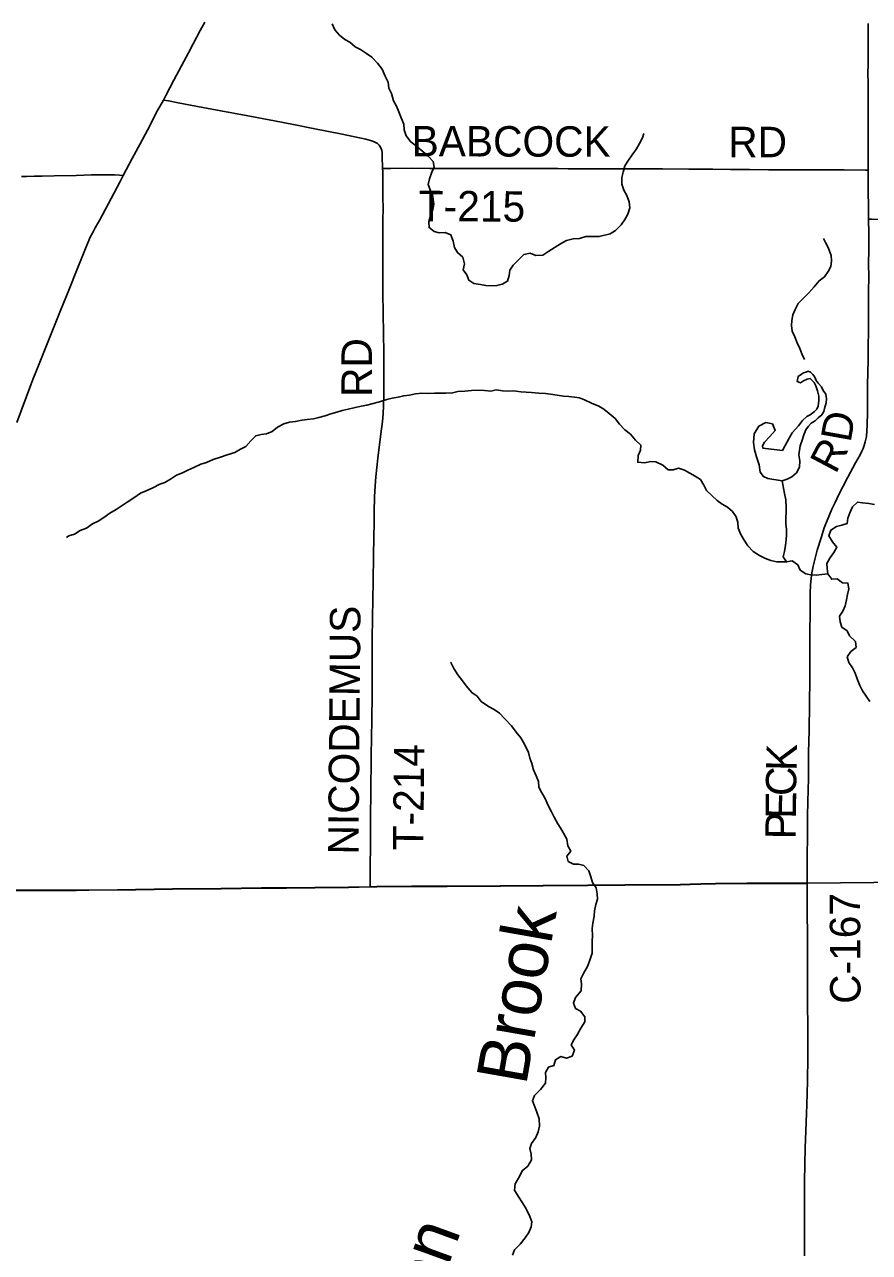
# Model space of a CAD drawing. Extents: x 0 to 34, y 0 to 22.
# Drawn here: x 26.211 to 27.787, y 14.945 to 17.236 of the extents above; entities that cross this region are included whole.
import ezdxf

# ---------------------------------------------------------------- set-up
doc = ezdxf.new("R2010")
doc.units = 0
for name, color, linetype in [('GM_X_Corporation', 7, 'Continuous'), ('GM_X_County_Road', 7, 'Continuous'), ('GM_X_County_Road_Text', 7, 'Continuous'), ('GM_X_Minor_Lake', 7, 'Continuous'), ('GM_X_Minor_River', 7, 'Continuous'), ('GM_X_Minor_River_Text', 7, 'Continuous'), ('GM_X_State_Route', 7, 'Continuous'), ('GM_X_Township_Road', 7, 'Continuous'), ('GM_X_Township_Road_Text', 7, 'Continuous')]:
    doc.layers.add(name, color=color, linetype=linetype)

msp = doc.modelspace()

# ---------------------------------------------------------------- linework, layer by layer
at = {"layer": 'GM_X_Corporation'}
for points in [[(28.234, 15.6398), (27.6706, 15.6341), (27.5944, 15.6337), (27.5583, 15.6337), (27.4999, 15.6332), (27.4725, 15.6325), (27.4525, 15.632), (27.4343, 15.6316), (27.3309, 15.6307), (27.2619, 15.6301), (27.2315, 15.6299), (27.178, 15.6296), (27.0985, 15.6292), (27.0326, 15.6286), (26.9991, 15.6286), (26.9326, 15.6281), (26.8679, 15.6275), (26.8556, 15.6273), (26.8151, 15.6267), (26.7523, 15.626), (26.6995, 15.6253), (26.6529, 15.625), (26.5776, 15.624), (26.4869, 15.6234), (26.4179, 15.6223), (26.3844, 15.6218), (26.3302, 15.6211), (26.3069, 15.621), (26.2122, 15.6211), (26.1856, 15.6206)], [(26.1856, 15.6206), (26.2122, 15.6211), (26.3069, 15.621), (26.3302, 15.6211), (26.3844, 15.6218), (26.4179, 15.6223), (26.4869, 15.6234), (26.5776, 15.624), (26.6529, 15.625), (26.6995, 15.6253), (26.7523, 15.626), (26.8151, 15.6267), (26.8556, 15.6273), (26.8679, 15.6275), (26.9326, 15.6281), (26.9991, 15.6286), (27.0326, 15.6286), (27.0985, 15.6292), (27.178, 15.6296), (27.2315, 15.6299), (27.2619, 15.6301), (27.3309, 15.6307), (27.4343, 15.6316), (27.4525, 15.632), (27.4725, 15.6325), (27.4999, 15.6332), (27.5583, 15.6337), (27.5944, 15.6337), (27.6706, 15.6341), (28.234, 15.6398)]]:
    msp.add_lwpolyline(points, dxfattribs=at)
at = {"layer": 'GM_X_County_Road'}
for points in [[(27.785, 16.9644), (27.7849, 16.9936), (27.7849, 17.0066), (27.7849, 17.0109), (27.7848, 17.0153), (27.7848, 17.0339), (27.7849, 17.0472), (27.7848, 17.0794), (27.7848, 17.1046), (27.7848, 17.1278), (27.7846, 17.1444), (27.785, 17.1634), (27.785, 17.1754), (27.785, 17.1878), (27.7848, 17.2189), (27.7849, 17.2294), (27.7851, 17.2381)], [(26.2052, 16.9526), (26.2151, 16.9528), (26.2287, 16.9531), (26.2435, 16.9533), (26.2661, 16.9537), (26.307, 16.9546), (26.3357, 16.9555), (26.3588, 16.9554), (26.3788, 16.9554), (26.3881, 16.955), (26.395, 16.9547)], [(27.7857, 16.8731), (27.7854, 16.8924), (27.7855, 16.9048), (27.7852, 16.9165), (27.7851, 16.9315), (27.7851, 16.9514), (27.7851, 16.9588), (27.785, 16.9644)], [(27.6708, 15.6335), (27.671, 15.6516), (27.6714, 15.6843), (27.6717, 15.7217), (27.672, 15.7602), (27.6724, 15.7857), (27.6729, 15.808), (27.6733, 15.8291), (27.6734, 15.8416), (27.6735, 15.8527), (27.6739, 15.8776), (27.6746, 15.9186), (27.6748, 15.9304), (27.6753, 15.9559), (27.6754, 15.9695), (27.6756, 15.9844), (27.6758, 15.9999), (27.676, 16.0335), (27.6762, 16.0596), (27.6763, 16.0838), (27.6762, 16.0944), (27.6763, 16.108), (27.6764, 16.1328), (27.6764, 16.1433), (27.6764, 16.1538), (27.6765, 16.1633), (27.6767, 16.1746), (27.6774, 16.1905), (27.6784, 16.2022), (27.6799, 16.2131), (27.682, 16.2252), (27.6858, 16.2402), (27.69, 16.2555), (27.697, 16.2782), (27.703, 16.2971), (27.7083, 16.3109), (27.7126, 16.3212), (27.7172, 16.3318), (27.7231, 16.3441), (27.7296, 16.3577), (27.7467, 16.3915), (27.7613, 16.4181), (27.7698, 16.4332), (27.7733, 16.4403), (27.7754, 16.4452), (27.7773, 16.4504), (27.7795, 16.4574), (27.7806, 16.4623), (27.7816, 16.4674), (27.7821, 16.4711), (27.7823, 16.4741), (27.7826, 16.4767), (27.7826, 16.4792), (27.7827, 16.4816), (27.7829, 16.485), (27.7832, 16.4949), (27.7835, 16.5067), (27.7837, 16.5185), (27.7839, 16.5313), (27.7837, 16.5485), (27.7839, 16.566), (27.7843, 16.5848), (27.7848, 16.6119), (27.7851, 16.6376), (27.7854, 16.6614), (27.7857, 16.6947), (27.7857, 16.7216), (27.7858, 16.7425), (27.7859, 16.7611), (27.7857, 16.7939), (27.7859, 16.8123), (27.7859, 16.8477), (27.7857, 16.872), (27.7857, 16.8731)], [(26.0069, 15.6183), (26.0273, 15.6184), (26.1615, 15.6197), (26.1858, 15.62), (26.2124, 15.6205), (26.3071, 15.6204), (26.3304, 15.6206), (26.3846, 15.6212), (26.4181, 15.6217), (26.4871, 15.6228), (26.5778, 15.6235), (26.6531, 15.6244), (26.6997, 15.6248), (26.7525, 15.6255), (26.8153, 15.6261), (26.8559, 15.6268)], [(26.8559, 15.6268), (26.8681, 15.627), (26.9328, 15.6276), (26.9993, 15.628), (27.0328, 15.6281), (27.0987, 15.6286), (27.1782, 15.6291), (27.2317, 15.6293), (27.2621, 15.6296), (27.3311, 15.6301), (27.4345, 15.6311), (27.4527, 15.6314), (27.4727, 15.632), (27.5001, 15.6327), (27.5585, 15.6332), (27.5946, 15.6332), (27.6708, 15.6335)], [(27.6661, 14.9388), (27.6659, 14.9743), (27.666, 14.988), (27.6659, 15.0054), (27.6659, 15.0246), (27.666, 15.0513), (27.6661, 15.0778), (27.6676, 15.1399), (27.6686, 15.1709), (27.67, 15.2047), (27.6705, 15.2197), (27.6716, 15.2647), (27.6723, 15.3101), (27.6723, 15.3225), (27.6723, 15.3741), (27.672, 15.4008), (27.672, 15.4219), (27.672, 15.4387), (27.6719, 15.499), (27.6718, 15.5288), (27.6713, 15.5866), (27.6708, 15.6335)]]:
    msp.add_lwpolyline(points, dxfattribs=at)
at = {"layer": 'GM_X_Minor_Lake'}
msp.add_line((27.598, 16.389), (27.6242, 16.3847), dxfattribs=at)
msp.add_lwpolyline([(27.6242, 16.3847), (27.634, 16.3879), (27.6423, 16.3921), (27.6509, 16.3998), (27.6568, 16.4101), (27.6575, 16.4223), (27.6554, 16.4329), (27.6583, 16.45), (27.6616, 16.4603), (27.6649, 16.4706), (27.6689, 16.4798), (27.6734, 16.4867), (27.6786, 16.4924), (27.6858, 16.4967), (27.6914, 16.5021), (27.6982, 16.5078), (27.7023, 16.514), (27.7033, 16.5197), (27.7066, 16.5303), (27.7073, 16.5376), (27.7057, 16.5467), (27.7007, 16.5534), (27.6976, 16.5599), (27.6918, 16.567), (27.688, 16.5719), (27.6856, 16.5779), (27.6814, 16.5828), (27.6772, 16.5877), (27.673, 16.5896), (27.6685, 16.5876), (27.664, 16.586), (27.6606, 16.5837), (27.6546, 16.5795), (27.6524, 16.5703), (27.6589, 16.5678), (27.6645, 16.5712), (27.6709, 16.5747), (27.6766, 16.5756), (27.6842, 16.5681), (27.687, 16.562), (27.6901, 16.5526), (27.6928, 16.5427), (27.6926, 16.5344), (27.6919, 16.5241), (27.689, 16.5184), (27.6841, 16.5134), (27.6766, 16.508), (27.6706, 16.5045), (27.6627, 16.4972), (27.6548, 16.4876), (27.6429, 16.4745), (27.6377, 16.4646), (27.6302, 16.4508), (27.625, 16.4413), (27.5883, 16.4458), (27.5878, 16.45), (27.5915, 16.4568), (27.6017, 16.4672), (27.6114, 16.4787), (27.6063, 16.4912), (27.5938, 16.4937), (27.581, 16.4867), (27.5721, 16.4726), (27.5707, 16.4562), (27.5728, 16.4426), (27.5767, 16.4297), (27.5818, 16.4146), (27.5835, 16.4006), (27.5896, 16.393), (27.598, 16.389)], dxfattribs=at)
at = {"layer": 'GM_X_Minor_River'}
for points in [[(26.7845, 17.2373), (26.7899, 17.2264), (26.7987, 17.2162), (26.8083, 17.208), (26.8178, 17.2031), (26.8277, 17.1945), (26.8376, 17.1893), (26.8491, 17.1822), (26.8586, 17.1751), (26.8694, 17.1642), (26.8778, 17.1526), (26.8836, 17.1397), (26.8891, 17.1284), (26.8903, 17.1174), (26.8954, 17.1072), (26.8993, 17.094), (26.9047, 17.0838), (26.909, 17.0732), (26.9137, 17.0622), (26.9187, 17.0505), (26.9192, 17.0395), (26.9231, 17.0285), (26.9308, 17.0176), (26.9431, 17.0079), (26.9538, 16.9993), (26.9637, 16.9903), (26.9733, 16.9805), (26.9753, 16.9699), (26.9709, 16.9604), (26.9661, 16.9485), (26.9639, 16.9375), (26.969, 16.9243), (26.9725, 16.9144), (26.9746, 16.9008), (26.9728, 16.8913), (26.968, 16.8798), (26.9654, 16.868), (26.9656, 16.8574), (26.9751, 16.8499), (26.9846, 16.8473), (26.9956, 16.8479), (27.0062, 16.8438), (27.0105, 16.8317), (27.0133, 16.8203), (27.0187, 16.8105), (27.0287, 16.8019), (27.0318, 16.7894), (27.0289, 16.7787), (27.0359, 16.769), (27.0398, 16.7591), (27.0493, 16.7532), (27.0614, 16.751), (27.0713, 16.7492), (27.0819, 16.7486), (27.0921, 16.7491), (27.1019, 16.7519), (27.1117, 16.7573), (27.115, 16.7676), (27.1164, 16.7775), (27.1224, 16.7874), (27.1325, 16.797), (27.1426, 16.807), (27.1543, 16.8098), (27.1646, 16.805), (27.1779, 16.8056), (27.1888, 16.8133), (27.2106, 16.8272), (27.2222, 16.8334), (27.2343, 16.8362), (27.2461, 16.8371), (27.2578, 16.8407), (27.2714, 16.8404), (27.2828, 16.8406), (27.3032, 16.8454), (27.3137, 16.8516), (27.3242, 16.8623), (27.3309, 16.8723), (27.3365, 16.8822), (27.3401, 16.894), (27.3389, 16.9054)], [(27.3389, 16.9054), (27.3349, 16.9171), (27.3291, 16.9273), (27.3252, 16.9383), (27.3255, 16.9504), (27.3276, 16.9607), (27.3309, 16.9722), (27.338, 16.9829), (27.3447, 16.9932), (27.3529, 17.0043), (27.3581, 17.0142), (27.364, 17.0249), (27.3666, 17.0329)], [(27.666, 16.6111), (27.6613, 16.6217), (27.6574, 16.6319), (27.6527, 16.6421), (27.6481, 16.6535), (27.6434, 16.6637), (27.6418, 16.6743), (27.6424, 16.6838), (27.6442, 16.6944), (27.6486, 16.7047), (27.6546, 16.7154), (27.6639, 16.725), (27.674, 16.7358), (27.6841, 16.7469), (27.6935, 16.758), (27.7032, 16.7654), (27.71, 16.7753), (27.7152, 16.7849), (27.7165, 16.7955), (27.7161, 16.8054), (27.7106, 16.8198), (27.7056, 16.8296), (27.7013, 16.8367)], [(27.7094, 16.211), (27.6985, 16.2098), (27.6879, 16.2085), (27.678, 16.2091), (27.6685, 16.2109), (27.6578, 16.218), (27.6536, 16.2282), (27.6429, 16.2353), (27.6327, 16.2333), (27.6145, 16.2338), (27.6035, 16.236), (27.5932, 16.2397), (27.5822, 16.2456), (27.5703, 16.2531), (27.5604, 16.2636), (27.5538, 16.2741), (27.5473, 16.2843), (27.5422, 16.2964), (27.5417, 16.3067), (27.5386, 16.3176), (27.532, 16.3274), (27.5225, 16.3353), (27.5125, 16.3412), (27.503, 16.3483), (27.493, 16.3573), (27.4831, 16.3667), (27.4781, 16.3765), (27.4719, 16.3871), (27.4623, 16.3931), (27.4524, 16.399), (27.4421, 16.4046), (27.4311, 16.4083), (27.4213, 16.4051), (27.4115, 16.4054), (27.4019, 16.414), (27.3889, 16.4199), (27.3795, 16.4206), (27.3674, 16.4182), (27.3549, 16.4195), (27.3555, 16.4317), (27.3603, 16.442), (27.3609, 16.4515), (27.351, 16.4605), (27.3414, 16.4718), (27.3307, 16.48), (27.3211, 16.4905), (27.3131, 16.5007), (27.3016, 16.5104), (27.2917, 16.5183), (27.2821, 16.5242), (27.2684, 16.5298), (27.2558, 16.5361), (27.2463, 16.5394), (27.2369, 16.5408), (27.2266, 16.5422), (27.2164, 16.5428), (27.1967, 16.5456), (27.1826, 16.5474), (27.1701, 16.5484), (27.1569, 16.5494), (27.147, 16.5504), (27.1371, 16.5506), (27.1239, 16.5524), (27.1117, 16.5522), (27.1023, 16.5529), (27.0905, 16.5543), (27.0807, 16.5523), (27.0689, 16.5533), (27.0576, 16.5539), (27.0447, 16.5534), (27.0326, 16.5521), (27.0193, 16.5512), (27.0095, 16.5488), (26.9967, 16.5482), (26.9754, 16.548), (26.9641, 16.5475), (26.9523, 16.5481), (26.9402, 16.5468), (26.9293, 16.5448), (26.9183, 16.5435), (26.9077, 16.5411), (26.8968, 16.5387), (26.8866, 16.5363), (26.873, 16.532), (26.859, 16.5284), (26.8492, 16.5256), (26.8386, 16.524), (26.8254, 16.5208), (26.8148, 16.5184), (26.8035, 16.516), (26.7933, 16.5128), (26.7823, 16.51), (26.7714, 16.5061), (26.7601, 16.5026), (26.7499, 16.5006), (26.7381, 16.4993), (26.7283, 16.4976), (26.7166, 16.4956), (26.7053, 16.494), (26.6943, 16.4912), (26.6826, 16.485)], [(26.6826, 16.485), (26.6725, 16.4765), (26.6623, 16.4726), (26.6525, 16.4713), (26.6423, 16.4689), (26.6329, 16.4593), (26.6236, 16.449), (26.6134, 16.4435), (26.6029, 16.4373), (26.5885, 16.433), (26.5761, 16.429), (26.5629, 16.4243), (26.5504, 16.4192), (26.5395, 16.4157), (26.5267, 16.4098), (26.5154, 16.4044), (26.5056, 16.3994), (26.4943, 16.395), (26.483, 16.3877), (26.4728, 16.3815), (26.463, 16.3783), (26.4498, 16.3717), (26.4378, 16.3659), (26.4268, 16.3616), (26.4144, 16.3527), (26.4024, 16.345), (26.3926, 16.3388), (26.3817, 16.3311), (26.3701, 16.3245), (26.3584, 16.316), (26.3479, 16.3094), (26.3377, 16.3044), (26.3261, 16.2962), (26.3147, 16.2919), (26.3038, 16.2854), (26.2933, 16.2818), (26.2891, 16.2787)], [(27.6327, 16.2333), (27.6265, 16.2431), (27.6287, 16.2526), (27.6308, 16.2644), (27.6322, 16.2743), (27.6325, 16.2842), (27.6328, 16.2937), (27.6315, 16.3043), (27.6314, 16.3161), (27.632, 16.3256), (27.6319, 16.335), (27.631, 16.3495), (27.629, 16.3612), (27.627, 16.3711), (27.6242, 16.3847)], [(27.7882, 15.9731), (27.7809, 15.9829), (27.7744, 15.9931), (27.7693, 16.0029), (27.7646, 16.015), (27.7607, 16.0256), (27.7557, 16.0358), (27.7488, 16.0459), (27.746, 16.0565), (27.7527, 16.0661), (27.7628, 16.0738), (27.7612, 16.0848), (27.7501, 16.0953), (27.7455, 16.1051), (27.7355, 16.1115), (27.7324, 16.1217), (27.7315, 16.1319), (27.7375, 16.1415), (27.7419, 16.1514), (27.7444, 16.1628), (27.7466, 16.1724), (27.7487, 16.183), (27.7471, 16.194), (27.7373, 16.1946), (27.7269, 16.2021), (27.7171, 16.2009), (27.7094, 16.211), (27.7082, 16.2209), (27.7077, 16.2304), (27.7136, 16.2407), (27.7207, 16.2507), (27.7267, 16.261), (27.7186, 16.2711), (27.7113, 16.2821), (27.7153, 16.2927), (27.7259, 16.2997), (27.7357, 16.3021), (27.7459, 16.3052), (27.7473, 16.3148), (27.751, 16.3247), (27.7554, 16.3361), (27.7651, 16.345), (27.7746, 16.3436), (27.7864, 16.3426), (27.7966, 16.3408)], [(27.1666, 15.2065), (27.1627, 15.2167), (27.1584, 15.228), (27.1625, 15.2379), (27.1733, 15.2491), (27.1827, 15.2606), (27.1837, 15.2705), (27.1828, 15.2807), (27.1884, 15.2906), (27.1986, 15.2938), (27.2015, 15.3045), (27.2116, 15.3103), (27.2223, 15.3077), (27.2325, 15.3113), (27.2369, 15.3223), (27.2307, 15.3321), (27.2355, 15.3417), (27.2422, 15.3512), (27.2489, 15.3635), (27.2564, 15.375), (27.2562, 15.3848), (27.2482, 15.395), (27.2386, 15.4002), (27.2351, 15.41), (27.2388, 15.4203), (27.2496, 15.4333), (27.2502, 15.4459), (27.2486, 15.4557), (27.2542, 15.4668), (27.2609, 15.4783), (27.2649, 15.4886), (27.2697, 15.5031), (27.2699, 15.5144), (27.2702, 15.5262), (27.2708, 15.5357), (27.2699, 15.5494), (27.2713, 15.5593), (27.2734, 15.5722), (27.2741, 15.5825), (27.2766, 15.5943), (27.2799, 15.6038), (27.279, 15.614), (27.2774, 15.6254), (27.2708, 15.6352), (27.2677, 15.6458), (27.2638, 15.6571), (27.2542, 15.6669), (27.2447, 15.6691), (27.2349, 15.6697), (27.2253, 15.6745), (27.2226, 15.6844), (27.23, 15.6939), (27.2242, 15.7038), (27.2226, 15.7163), (27.2133, 15.7329), (27.206, 15.7445), (27.199, 15.757), (27.194, 15.7672), (27.1878, 15.7789), (27.182, 15.7921), (27.1758, 15.8023), (27.1707, 15.8132), (27.1695, 15.8235), (27.1656, 15.8344), (27.1605, 15.8454), (27.1574, 15.8571), (27.1539, 15.8673), (27.1511, 15.8779), (27.1441, 15.8923), (27.1371, 15.9051), (27.1279, 15.9156), (27.1195, 15.9273), (27.1072, 15.9405), (27.0972, 15.9513), (27.0873, 15.9577), (27.0763, 15.9636), (27.0629, 15.973), (27.0552, 15.9828), (27.0453, 15.9895), (27.0349, 16.0019), (27.028, 16.0117), (27.0192, 16.0226), (27.0115, 16.0343), (27.0064, 16.046), (27.0068, 16.0452)], [(27.1211, 14.9398), (27.1252, 14.9497), (27.1353, 14.9601), (27.145, 14.972), (27.1517, 14.9823), (27.1558, 14.9926), (27.1572, 15.0021), (27.1537, 15.012), (27.1467, 15.0263), (27.1401, 15.0372), (27.132, 15.0497), (27.1251, 15.0614), (27.1261, 15.0731), (27.1342, 15.0869), (27.1391, 15.0972), (27.1496, 15.1057), (27.1566, 15.1175), (27.1561, 15.1281), (27.1537, 15.1388), (27.1567, 15.1483), (27.1645, 15.1594), (27.1693, 15.1697), (27.1718, 15.1807), (27.1709, 15.1944), (27.1666, 15.2065)]]:
    msp.add_lwpolyline(points, dxfattribs=at)
at = {"layer": 'GM_X_State_Route'}
msp.add_lwpolyline([(26.1961, 16.4933), (26.2226, 16.5637), (26.2264, 16.5735), (26.2331, 16.5903), (26.2778, 16.7023), (26.2932, 16.7402), (26.309, 16.7794), (26.3194, 16.806), (26.3258, 16.8215), (26.3306, 16.8329), (26.3328, 16.838), (26.3388, 16.8496), (26.3427, 16.8567), (26.3469, 16.8643), (26.351, 16.872), (26.3665, 16.901), (26.389, 16.9432), (26.395, 16.9547), (26.4116, 16.9861), (26.4262, 17.0135), (26.44, 17.0393), (26.4591, 17.0755), (26.4697, 17.0952), (26.4744, 17.104), (26.4894, 17.1326), (26.5033, 17.1589), (26.5165, 17.1836), (26.5252, 17.2001), (26.5386, 17.2253), (26.5469, 17.2406)], dxfattribs=at)
at = {"layer": 'GM_X_Township_Road'}
for points in [[(26.8788, 16.9675), (26.8786, 16.9736), (26.8783, 16.9848), (26.8783, 16.9879), (26.8781, 16.998), (26.8774, 17.0012), (26.8763, 17.0048), (26.8738, 17.0093), (26.8726, 17.0108), (26.8693, 17.0139), (26.8667, 17.0157), (26.8621, 17.018), (26.8561, 17.02), (26.8476, 17.0221), (26.8037, 17.0313), (26.7495, 17.0424), (26.7123, 17.0494), (26.6769, 17.0566), (26.6244, 17.0666), (26.5767, 17.0753), (26.5432, 17.0816), (26.4974, 17.0901), (26.4791, 17.0935), (26.4697, 17.0952)], [(26.8559, 15.6268), (26.8559, 15.6336), (26.8559, 15.6732), (26.8563, 15.6961), (26.8564, 15.7123), (26.8565, 15.7272), (26.8564, 15.7527), (26.857, 15.8086), (26.8571, 15.8267), (26.8574, 15.8453), (26.8578, 15.8776), (26.858, 15.9), (26.8587, 15.9435), (26.8591, 15.9802), (26.8593, 16.0081), (26.8594, 16.0292), (26.8591, 16.0578), (26.8595, 16.0889), (26.8603, 16.1299), (26.8614, 16.197), (26.8618, 16.2455), (26.8624, 16.2797), (26.8629, 16.307), (26.863, 16.3269), (26.8638, 16.3548), (26.8648, 16.3753), (26.8662, 16.392), (26.87, 16.4272), (26.8756, 16.4722), (26.8785, 16.4957), (26.8799, 16.5099), (26.8808, 16.5255), (26.881, 16.5423), (26.8811, 16.5715), (26.8812, 16.592), (26.8811, 16.6231), (26.8805, 16.6604), (26.8799, 16.6964), (26.8794, 16.7362), (26.8795, 16.7648), (26.8794, 16.8008), (26.8795, 16.8418), (26.8795, 16.8754), (26.8796, 16.8891), (26.8792, 16.9177), (26.8791, 16.9431), (26.879, 16.9618), (26.8788, 16.9675)], [(26.8788, 16.9675), (26.8839, 16.9676), (26.8942, 16.9677), (26.934, 16.9679), (26.967, 16.9677), (27.0071, 16.9677), (27.0413, 16.9674), (27.078, 16.9676), (27.1283, 16.9678), (27.1631, 16.9677), (27.206, 16.9673), (27.2252, 16.967), (27.2495, 16.9666), (27.2719, 16.9668), (27.3153, 16.9666), (27.3359, 16.9667), (27.3483, 16.9668), (27.4014, 16.9666), (27.4501, 16.9663), (27.4951, 16.966), (27.5278, 16.9655), (27.5638, 16.9655), (27.5992, 16.9652), (27.652, 16.9651), (27.6646, 16.965), (27.6911, 16.965), (27.7166, 16.9649), (27.7401, 16.9648), (27.7801, 16.9645), (27.785, 16.9644)], [(27.7857, 16.8731), (27.7916, 16.873), (27.8621, 16.8722), (27.9719, 16.8711), (27.9793, 16.8705), (27.9864, 16.8689), (27.9898, 16.8677), (27.9937, 16.866), (27.9996, 16.8626), (28.0046, 16.8591), (28.0106, 16.8548), (28.0138, 16.8522)]]:
    msp.add_lwpolyline(points, dxfattribs=at)

# ---------------------------------------------------------------- texts
at = {"layer": 'GM_X_County_Road_Text'}
for s, height, rotation, p in [('D', 0.0568, 79.8842, (27.752, 16.4549)), ('R', 0.0568, 62.1013, (27.7241, 16.3958)), ('K', 0.0568, 88.7286, (27.6511, 15.8429)), ('C', 0.0568, 89.395, (27.6506, 15.7964)), ('E', 0.0568, 89.4129, (27.6502, 15.7539)), ('P', 0.0568, 89.4156, (27.6498, 15.7156)), ('C-167', 0.05682, 90.2751, (27.7708, 15.4088))]:
    msp.add_text(s, height=height, rotation=rotation, dxfattribs=at).set_placement(p)
at = {"layer": 'GM_X_Minor_River_Text'}
for s, height, rotation, p in [('Brook', 0.09473, 79.9852, (27.1465, 15.2551)), ('Harmon', 0.09471, 69.9863, (26.8714, 14.5616))]:
    msp.add_text(s, height=height, rotation=rotation, dxfattribs=at).set_placement(p)
at = {"layer": 'GM_X_Township_Road_Text'}
for s, rotation, p in [('BABCOCK', 359.8583, (26.9329, 16.9902)), ('RD', 0, (27.5238, 16.9885)), ('T-215', 359.7181, (26.9463, 16.8692)), ('RD', 90, (26.8589, 16.5412)), ('NICODEMUS', 89.5401, (26.8339, 15.6872)), ('T-214', 89.4555, (26.9549, 15.6948))]:
    msp.add_text(s, height=0.05682, rotation=rotation, dxfattribs=at).set_placement(p)

doc.saveas('drawing.dxf')
